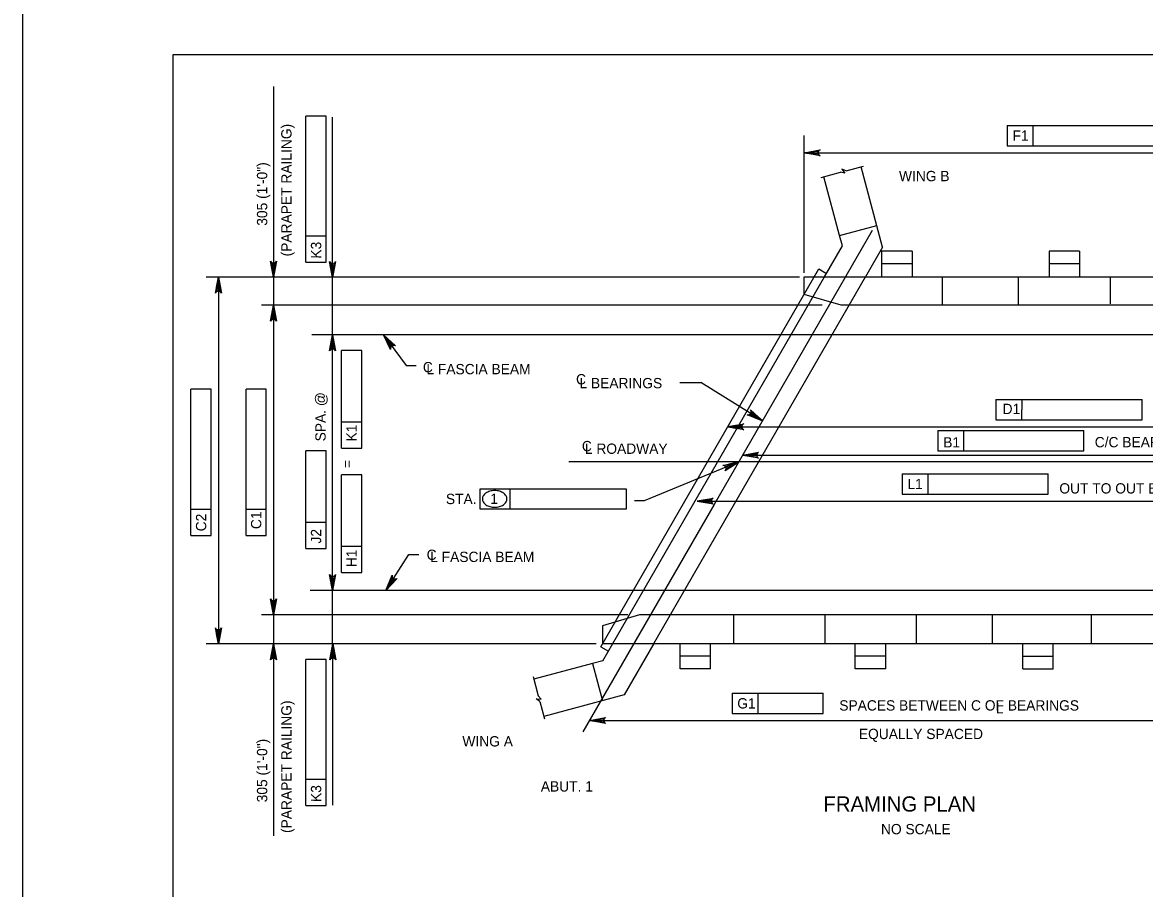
# Model space of a CAD drawing. Extents: x -13 to 81, y -176 to 0.
# Drawn here: x 0 to 13.06, y -120.46 to -110.38 of the extents above; entities that cross this region are included whole.
import ezdxf

# ---------------------------------------------------------------- set-up
doc = ezdxf.new("R2010")
doc.units = 0
for name, color, linetype in [('Level 1', 7, 'Continuous'), ('Level 2', 7, 'Continuous'), ('Level 3', 7, 'Continuous'), ('Level 4', 7, 'Continuous'), ('Level 63', 7, 'Continuous')]:
    doc.layers.add(name, color=color, linetype=linetype)

# ---------------------------------------------------------------- blocks, each defined once
blk = doc.blocks.new('AR')
at = {"layer": 'Level 4'}
blk.add_lwpolyline([(3.33, 0.56), (3.33, -0.56), (0, 0)], close=True, dxfattribs=at)

msp = doc.modelspace()

# ---------------------------------------------------------------- linework, layer by layer
at = {"layer": 'Level 1'}
msp.add_lwpolyline([(1.75, -131.25), (33.25, -131.25), (33.25, -110.75), (1.75, -110.75)], close=True, dxfattribs=at)
at = {"layer": 'Level 2'}
for p, q in [((10.014, -112.992), (9.763, -112.055)), ((9.514, -112.854), (9.331, -112.17)), ((9.514, -112.854), (9.946, -112.738)), ((9.546, -112.975), (9.514, -112.854)), ((9.339, -113.334), (9.546, -112.975)), ((10.014, -112.992), (9.816, -113.334)), ((10.003, -113.038), (10.003, -113.334)), ((10.358, -113.038), (10.003, -113.038)), ((10.358, -113.038), (10.358, -113.334)), ((11.952, -113.038), (11.952, -113.334)), ((12.307, -113.038), (11.952, -113.038)), ((12.307, -113.038), (12.307, -113.334)), ((6.733, -117.641), (9.272, -113.244)), ((9.272, -113.244), (9.361, -113.296)), ((6.874, -117.603), (9.339, -113.334)), ((7.352, -117.603), (9.816, -113.334)), ((9.101, -113.334), (17.286, -113.334)), ((9.101, -113.54), (9.101, -113.334)), ((9.53, -113.666), (9.101, -113.54)), ((16.857, -113.666), (9.53, -113.666)), ((7.184, -117.271), (6.755, -117.396)), ((14.511, -117.271), (7.184, -117.271)), ((6.755, -117.396), (6.755, -117.603)), ((6.733, -117.641), (6.823, -117.693)), ((6.755, -117.603), (14.941, -117.603)), ((6.758, -117.805), (6.874, -117.603)), ((7.352, -117.603), (7.007, -118.201)), ((7.658, -117.898), (7.658, -117.603)), ((8.012, -117.898), (8.012, -117.603)), ((9.696, -117.898), (9.696, -117.603)), ((10.05, -117.898), (10.05, -117.603)), ((11.646, -117.898), (11.646, -117.603)), ((12, -117.898), (12, -117.603)), ((6.758, -117.805), (6.637, -117.837)), ((6.637, -117.837), (5.954, -118.02)), ((6.637, -117.837), (6.753, -118.269)), ((8.012, -117.898), (7.658, -117.898)), ((10.05, -117.898), (9.696, -117.898)), ((11.646, -117.898), (12, -117.898)), ((7.007, -118.201), (6.069, -118.452))]:
    msp.add_line(p, q, dxfattribs=at)
at = {"layer": 'Level 3'}
for p, q in [((9.588, -112.102), (9.54, -112.081)), ((9.54, -112.081), (9.573, -112.131)), ((9.588, -112.102), (9.793, -112.047)), ((9.298, -112.179), (9.522, -112.119)), ((9.573, -112.131), (9.522, -112.119)), ((10.358, -113.186), (10.003, -113.186)), ((12.307, -113.186), (11.952, -113.186)), ((10.712, -113.666), (10.712, -113.334)), ((11.598, -113.666), (11.598, -113.334)), ((12.662, -113.334), (12.662, -113.65)), ((8.278, -117.271), (8.278, -117.603)), ((9.341, -117.271), (9.341, -117.603)), ((10.405, -117.271), (10.405, -117.603)), ((11.291, -117.271), (11.291, -117.603)), ((12.443, -117.271), (12.443, -117.603)), ((8.012, -117.75), (7.658, -117.75)), ((10.05, -117.75), (9.696, -117.75)), ((11.646, -117.75), (12, -117.75)), ((5.945, -117.987), (6.005, -118.211)), ((6.04, -118.25), (6.005, -118.211)), ((5.981, -118.246), (6.04, -118.25)), ((6.023, -118.277), (5.981, -118.246)), ((6.023, -118.277), (6.078, -118.482))]:
    msp.add_line(p, q, dxfattribs=at)
at = {"layer": 'Level 4'}
for p, q in [((2.923, -111.121), (2.923, -119.843)), ((3.536, -111.464), (3.3, -111.464)), ((3.3, -112.862), (3.3, -111.464)), ((3.536, -113.165), (3.536, -111.464)), ((3.611, -114.356), (3.611, -111.479)), ((9.101, -113.291), (9.101, -111.691)), ((11.466, -111.574), (11.768, -111.574)), ((11.466, -111.574), (11.466, -111.81)), ((11.768, -111.81), (11.768, -111.574)), ((11.768, -111.574), (13.167, -111.574)), ((11.466, -111.81), (13.166, -111.81)), ((9.101, -111.891), (17.286, -111.891)), ((3.3, -113.165), (3.3, -112.862)), ((3.536, -112.863), (3.3, -112.862)), ((9.894, -112.798), (8.055, -115.984)), ((3.611, -113.232), (3.611, -113.118)), ((3.3, -113.165), (3.536, -113.165)), ((9.048, -113.34), (2.14, -113.34)), ((2.281, -113.34), (2.281, -117.609)), ((9.312, -113.666), (2.783, -113.666)), ((17.29, -114.012), (3.368, -114.012)), ((4.202, -114.012), (4.469, -114.369)), ((3.95, -114.193), (3.714, -114.193)), ((3.714, -115.027), (3.714, -114.193)), ((3.95, -115.329), (3.95, -114.193)), ((3.611, -117.609), (3.611, -114.356)), ((4.469, -114.369), (4.583, -114.369)), ((7.654, -114.565), (7.899, -114.565)), ((8.616, -115.012), (7.899, -114.565)), ((2.198, -114.645), (1.962, -114.645)), ((1.962, -116.043), (1.962, -114.645)), ((2.198, -116.346), (2.198, -114.645)), ((2.839, -114.645), (2.603, -114.645)), ((2.603, -116.043), (2.603, -114.645)), ((2.839, -116.346), (2.839, -114.645)), ((11.334, -114.764), (11.637, -114.764)), ((11.334, -114.764), (11.334, -115.001)), ((11.636, -115.001), (11.637, -114.764)), ((11.637, -114.764), (13.035, -114.764)), ((13.035, -115.001), (13.035, -114.764)), ((3.714, -115.329), (3.714, -115.027)), ((3.95, -115.027), (3.714, -115.027)), ((8.212, -115.081), (16.264, -115.081)), ((11.334, -115.001), (13.035, -115.001)), ((10.656, -115.126), (10.958, -115.126)), ((10.656, -115.126), (10.656, -115.362)), ((10.958, -115.362), (10.958, -115.126)), ((10.958, -115.126), (12.357, -115.126)), ((12.357, -115.362), (12.357, -115.126)), ((3.714, -115.329), (3.95, -115.329)), ((3.536, -115.36), (3.3, -115.36)), ((3.3, -116.194), (3.3, -115.36)), ((3.536, -116.496), (3.536, -115.36)), ((8.385, -115.412), (15.735, -115.412)), ((10.656, -115.362), (12.357, -115.362)), ((18.053, -115.491), (6.361, -115.491)), ((8.339, -115.491), (7.24, -115.944)), ((3.95, -115.642), (3.714, -115.642)), ((3.714, -116.476), (3.714, -115.642)), ((3.95, -116.779), (3.95, -115.642)), ((10.242, -115.629), (10.241, -115.865)), ((10.242, -115.629), (10.544, -115.629)), ((10.544, -115.865), (10.544, -115.629)), ((10.544, -115.629), (11.942, -115.629)), ((11.942, -115.865), (11.942, -115.629)), ((5.329, -115.802), (5.678, -115.802)), ((5.329, -116.039), (5.329, -115.802)), ((5.678, -116.039), (5.678, -115.802)), ((5.678, -115.802), (7.029, -115.802)), ((7.029, -115.802), (7.029, -116.039)), ((10.241, -115.865), (11.942, -115.865)), ((8.055, -115.984), (6.525, -118.633)), ((7.24, -115.944), (7.127, -115.944)), ((7.856, -115.946), (15.658, -115.946)), ((1.962, -116.346), (1.962, -116.043)), ((2.198, -116.043), (1.962, -116.043)), ((2.603, -116.346), (2.603, -116.043)), ((2.839, -116.043), (2.603, -116.043)), ((7.029, -116.039), (5.329, -116.039)), ((3.3, -116.496), (3.3, -116.194)), ((3.536, -116.194), (3.3, -116.194)), ((1.962, -116.346), (2.198, -116.346)), ((2.603, -116.346), (2.839, -116.346)), ((3.3, -116.496), (3.536, -116.496)), ((3.714, -116.778), (3.714, -116.476)), ((3.95, -116.476), (3.714, -116.476)), ((4.232, -116.986), (4.5, -116.569)), ((4.5, -116.569), (4.614, -116.569)), ((3.714, -116.778), (3.95, -116.779)), ((15.74, -116.986), (3.349, -116.986)), ((7.049, -117.271), (2.783, -117.271)), ((6.678, -117.609), (2.14, -117.609)), ((3.536, -117.788), (3.3, -117.788)), ((3.3, -119.186), (3.3, -117.788)), ((3.536, -119.489), (3.536, -117.788)), ((3.611, -117.718), (3.611, -117.831)), ((3.611, -117.831), (3.611, -119.486)), ((8.264, -118.182), (8.566, -118.182)), ((8.264, -118.182), (8.264, -118.418)), ((8.566, -118.418), (8.566, -118.182)), ((8.566, -118.182), (9.324, -118.182)), ((9.324, -118.418), (9.324, -118.182)), ((8.264, -118.418), (9.324, -118.418)), ((6.603, -118.499), (13.953, -118.499)), ((3.3, -119.488), (3.3, -119.186)), ((3.536, -119.186), (3.3, -119.186)), ((3.3, -119.488), (3.536, -119.489))]:
    msp.add_line(p, q, dxfattribs=at)
for points in [[(9.101, -111.891), (9.287, -111.856), (9.273, -111.866), (9.265, -111.878), (9.263, -111.891), (9.265, -111.903), (9.273, -111.916), (9.287, -111.926), (9.101, -111.891), (9.273, -111.916), (9.265, -111.903), (9.101, -111.891), (9.263, -111.891), (9.265, -111.878), (9.101, -111.891), (9.273, -111.866)], [(2.923, -113.34), (2.888, -113.153), (2.898, -113.168), (2.911, -113.175), (2.923, -113.177), (2.936, -113.175), (2.948, -113.168), (2.958, -113.153), (2.923, -113.34), (2.948, -113.168), (2.936, -113.175), (2.923, -113.34), (2.923, -113.177), (2.911, -113.175), (2.923, -113.34), (2.898, -113.168)], [(3.611, -113.345), (3.576, -113.159), (3.586, -113.173), (3.599, -113.181), (3.611, -113.183), (3.624, -113.181), (3.636, -113.173), (3.646, -113.159), (3.611, -113.345), (3.636, -113.173), (3.624, -113.181), (3.611, -113.345), (3.611, -113.183), (3.599, -113.181), (3.611, -113.345), (3.586, -113.173)], [(2.281, -113.34), (2.316, -113.526), (2.306, -113.512), (2.293, -113.504), (2.281, -113.502), (2.268, -113.504), (2.256, -113.512), (2.246, -113.526), (2.281, -113.34), (2.256, -113.512), (2.268, -113.504), (2.281, -113.34), (2.281, -113.502), (2.293, -113.504), (2.281, -113.34), (2.306, -113.512)], [(2.923, -113.666), (2.958, -113.852), (2.948, -113.838), (2.936, -113.831), (2.923, -113.828), (2.911, -113.831), (2.898, -113.838), (2.888, -113.852), (2.923, -113.666), (2.898, -113.838), (2.911, -113.831), (2.923, -113.666), (2.923, -113.828), (2.936, -113.831), (2.923, -113.666), (2.948, -113.838)], [(3.611, -114.012), (3.646, -114.198), (3.636, -114.184), (3.624, -114.177), (3.611, -114.174), (3.599, -114.177), (3.586, -114.184), (3.576, -114.198), (3.611, -114.012), (3.586, -114.184), (3.599, -114.177), (3.611, -114.012), (3.611, -114.174), (3.624, -114.177), (3.611, -114.012), (3.636, -114.184)], [(4.202, -114.012), (4.342, -114.14), (4.325, -114.135), (4.311, -114.136), (4.3, -114.142), (4.291, -114.151), (4.285, -114.165), (4.286, -114.182), (4.202, -114.012), (4.285, -114.165), (4.291, -114.151), (4.202, -114.012), (4.3, -114.142), (4.311, -114.136), (4.202, -114.012), (4.325, -114.135)], [(8.616, -115.012), (8.439, -114.943), (8.457, -114.942), (8.47, -114.935), (8.478, -114.926), (8.483, -114.914), (8.483, -114.9), (8.476, -114.884), (8.616, -115.012), (8.483, -114.9), (8.483, -114.914), (8.616, -115.012), (8.478, -114.926), (8.47, -114.935), (8.616, -115.012), (8.457, -114.942)], [(8.212, -115.081), (8.399, -115.046), (8.384, -115.056), (8.377, -115.069), (8.375, -115.081), (8.377, -115.094), (8.384, -115.106), (8.399, -115.116), (8.212, -115.081), (8.384, -115.106), (8.377, -115.094), (8.212, -115.081), (8.375, -115.081), (8.377, -115.069), (8.212, -115.081), (8.384, -115.056)], [(8.385, -115.412), (8.571, -115.377), (8.557, -115.387), (8.55, -115.4), (8.547, -115.412), (8.55, -115.425), (8.557, -115.437), (8.571, -115.447), (8.385, -115.412), (8.557, -115.437), (8.55, -115.425), (8.385, -115.412), (8.547, -115.412), (8.55, -115.4), (8.385, -115.412), (8.557, -115.387)], [(8.339, -115.491), (8.18, -115.594), (8.19, -115.58), (8.192, -115.565), (8.189, -115.553), (8.182, -115.542), (8.171, -115.533), (8.154, -115.53), (8.339, -115.491), (8.171, -115.533), (8.182, -115.542), (8.339, -115.491), (8.189, -115.553), (8.192, -115.565), (8.339, -115.491), (8.19, -115.58)], [(7.856, -115.946), (8.043, -115.911), (8.028, -115.921), (8.021, -115.934), (8.019, -115.946), (8.021, -115.959), (8.028, -115.971), (8.043, -115.981), (7.856, -115.946), (8.028, -115.971), (8.021, -115.959), (7.856, -115.946), (8.019, -115.946), (8.021, -115.934), (7.856, -115.946), (8.028, -115.921)], [(3.611, -116.986), (3.576, -116.8), (3.586, -116.814), (3.599, -116.821), (3.611, -116.824), (3.624, -116.821), (3.636, -116.814), (3.646, -116.8), (3.611, -116.986), (3.636, -116.814), (3.624, -116.821), (3.611, -116.986), (3.611, -116.824), (3.599, -116.821), (3.611, -116.986), (3.586, -116.814)], [(4.232, -116.986), (4.303, -116.81), (4.304, -116.828), (4.31, -116.841), (4.32, -116.849), (4.332, -116.854), (4.346, -116.855), (4.362, -116.848), (4.232, -116.986), (4.346, -116.855), (4.332, -116.854), (4.232, -116.986), (4.32, -116.849), (4.31, -116.841), (4.232, -116.986), (4.304, -116.828)], [(2.923, -117.271), (2.888, -117.084), (2.898, -117.099), (2.911, -117.106), (2.923, -117.108), (2.936, -117.106), (2.948, -117.099), (2.958, -117.084), (2.923, -117.271), (2.948, -117.099), (2.936, -117.106), (2.923, -117.271), (2.923, -117.108), (2.911, -117.106), (2.923, -117.271), (2.898, -117.099)], [(2.281, -117.609), (2.246, -117.422), (2.256, -117.437), (2.268, -117.444), (2.281, -117.446), (2.293, -117.444), (2.306, -117.437), (2.316, -117.422), (2.281, -117.609), (2.306, -117.437), (2.293, -117.444), (2.281, -117.609), (2.281, -117.446), (2.268, -117.444), (2.281, -117.609), (2.256, -117.437)], [(2.923, -117.609), (2.958, -117.795), (2.948, -117.781), (2.936, -117.773), (2.923, -117.771), (2.911, -117.773), (2.898, -117.781), (2.888, -117.795), (2.923, -117.609), (2.898, -117.781), (2.911, -117.773), (2.923, -117.609), (2.923, -117.771), (2.936, -117.773), (2.923, -117.609), (2.948, -117.781)], [(3.612, -117.609), (3.647, -117.795), (3.637, -117.781), (3.625, -117.773), (3.612, -117.771), (3.6, -117.773), (3.587, -117.781), (3.577, -117.795), (3.612, -117.609), (3.587, -117.781), (3.6, -117.773), (3.612, -117.609), (3.612, -117.771), (3.625, -117.773), (3.612, -117.609), (3.637, -117.781)], [(6.603, -118.499), (6.789, -118.464), (6.775, -118.474), (6.767, -118.486), (6.765, -118.499), (6.767, -118.511), (6.775, -118.524), (6.789, -118.534), (6.603, -118.499), (6.775, -118.524), (6.767, -118.511), (6.603, -118.499), (6.765, -118.499), (6.767, -118.486), (6.603, -118.499), (6.775, -118.474)]]:
    msp.add_lwpolyline(points, dxfattribs=at)
for points in [[(3.592, -113.232), (3.63, -113.232), (3.611, -113.345)], [(3.592, -114.125), (3.63, -114.125), (3.611, -114.012)], [(4.255, -114.114), (4.285, -114.091), (4.202, -114.012)], [(8.53, -114.936), (8.51, -114.968), (8.616, -115.012)], [(8.326, -115.1), (8.326, -115.062), (8.212, -115.081)], [(8.227, -115.517), (8.242, -115.552), (8.339, -115.491)], [(7.97, -115.965), (7.97, -115.927), (7.856, -115.946)], [(3.592, -116.873), (3.63, -116.873), (3.611, -116.986)], [(3.592, -117.718), (3.63, -117.718), (3.611, -117.604)]]:
    msp.add_lwpolyline(points, close=True, dxfattribs=at)
for centre, radius, start, end in [((5.458, -115.943), 0.11, 124.109, 148.5507), ((5.482, -115.979), 0.153, 105.6708, 124.109), ((5.498, -116.035), 0.211, 90, 105.6708), ((5.498, -116.035), 0.211, 74.3292, 90), ((5.514, -115.979), 0.153, 55.891, 74.3292), ((5.538, -115.943), 0.11, 31.4493, 55.891), ((5.422, -115.921), 0.067, 148.5507, 180), ((5.422, -115.921), 0.067, 180, 211.4493), ((5.458, -115.899), 0.11, 211.4493, 235.891), ((5.482, -115.863), 0.153, 235.891, 254.3292), ((5.514, -115.863), 0.153, 285.6708, 304.109), ((5.538, -115.899), 0.11, 304.109, 328.5507), ((5.574, -115.921), 0.067, 0, 31.4493), ((5.574, -115.921), 0.067, 328.5507, 0), ((5.498, -115.807), 0.211, 254.3292, 270), ((5.498, -115.807), 0.211, 270, 285.6708)]:
    msp.add_arc(centre, radius, start, end, dxfattribs=at)
at = {"layer": 'Level 63'}
msp.add_lwpolyline([(0, -132), (34, -132), (34, -110), (0, -110)], close=True, dxfattribs=at)

# ---------------------------------------------------------------- block references
at = {"layer": 'Level 4', "xscale": 0.035433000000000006, "yscale": 0.035433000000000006}
for p, rotation in [((2.923, -113.34), 90), ((2.281, -113.34), -90.00000000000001), ((2.923, -113.666), -90.00000000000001), ((2.923, -117.271), 90), ((2.281, -117.609), 90), ((2.923, -117.609), -90.00000000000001)]:
    msp.add_blockref('AR', p, dxfattribs=dict(at, rotation=rotation))
for p in [(8.385, -115.412), (6.603, -118.499)]:
    msp.add_blockref('AR', p, dxfattribs=at)

# ---------------------------------------------------------------- texts
at = {"layer": 'Level 4'}
for s, rotation, p in [('(PARAPET RAILING)', 90, (3.133, -113.098)), ('F1', 359.9382, (11.526, -111.752)), ('305 (1\'-0")', 90, (2.85, -112.741)), ('K3', 89.9382, (3.478, -113.124)), ('SPA. @', 90, (3.53, -115.251)), ('D1', 359.9382, (11.411, -114.933)), ('K1', 89.9382, (3.892, -115.252)), ('B1', 359.9382, (10.72, -115.322)), ('=', 90, (3.839, -115.561)), ('L1', 359.9382, (10.303, -115.807)), ('C2', 89.9382, (2.14, -116.298)), ('C1', 89.9382, (2.781, -116.272)), ('J2', 89.9382, (3.478, -116.44)), ('H1', 89.9382, (3.892, -116.716)), ('(PARAPET RAILING)', 90, (3.133, -119.809)), ('G1', 359.9382, (8.322, -118.36)), ('305 (1\'-0")', 90, (2.85, -119.452)), ('K3', 89.9382, (3.478, -119.448))]:
    msp.add_text(s, height=0.12, rotation=rotation, dxfattribs=at).set_placement(p)
for s, height, p in [('WING B', 0.12, (10.205, -112.223)), ('C', 0.12, (4.662, -114.447)), ('L FASCIA BEAM', 0.12, (4.703, -114.47)), ('C', 0.12, (6.445, -114.588)), ('L BEARINGS', 0.12, (6.485, -114.633)), ('C/C BEARINGS', 0.12, (12.484, -115.32)), ('C', 0.12, (6.513, -115.366)), ('L ROADWAY', 0.12, (6.548, -115.396)), ('OUT TO OUT BEAM', 0.12, (12.072, -115.858)), ('STA.', 0.12, (4.93, -115.981)), ('1', 0.12, (5.446, -115.979)), ('C', 0.12, (4.706, -116.631)), ('L FASCIA BEAM', 0.12, (4.747, -116.655)), ('SPACES BETWEEN C OF BEARINGS', 0.12, (9.51, -118.384)), ('L', 0.12, (11.332, -118.417)), ('EQUALLY SPACED', 0.12, (9.738, -118.716)), ('WING A', 0.12, (5.122, -118.802)), ('ABUT. 1', 0.12, (6.035, -119.327)), ('FRAMING PLAN', 0.17717, (9.325, -119.56)), ('NO SCALE', 0.12, (9.995, -119.824))]:
    msp.add_text(s, height=height, dxfattribs=at).set_placement(p)

doc.saveas('drawing.dxf')
